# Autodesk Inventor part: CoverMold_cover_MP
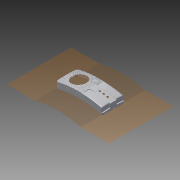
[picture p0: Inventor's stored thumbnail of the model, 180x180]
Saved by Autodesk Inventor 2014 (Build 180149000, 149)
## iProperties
Created: 2009-12
Part Number: CoverMold_cover_MP
Document SubType Name: Modeling
Designer: gaom
Density: 1 g/cm^3
Material: Generic
Appearance: Default
Author: gaom
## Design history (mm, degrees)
derived "cover.ipt"
node "CoverMold_cover_WP"
node "Hole Patch1"
patch "Boundary Patch1" dims "d7" = 10, "d8" = 0
node "Hole Patch2"
node "Hole Patch3"
patch "Boundary Patch2" dims "d9" = 10, "d10" = 10, "d11" = 10, "d12" = 10, "d13" = 0
node "Hole Patch4"
node "Runoff17" dims "Xmax" = 175, "Xmin" = -175, "Ymax" = 110, "Ymin" = -110, "Zmax" = 60, "Zmin" = -60
node "Runoff18" dims "Xmax" = 175, "Xmin" = -175, "Ymax" = 110, "Ymin" = -110, "Zmax" = 60, "Zmin" = -60
node "Runoff19" dims "Xmax" = 175, "Xmin" = -175, "Ymax" = 110, "Ymin" = -110, "Zmax" = 60, "Zmin" = -60
node "Runoff20" dims "Xmax" = 175, "Xmin" = -175, "Ymax" = 110, "Ymin" = -110, "Zmax" = 60, "Zmin" = -60
node "Runoff1" dims "Xmax" = 175, "Xmin" = -175, "Ymax" = 110, "Ymin" = -110, "Zmax" = 60, "Zmin" = -60
node "Runoff2" dims "Xmax" = 175, "Xmin" = -175, "Ymax" = 110, "Ymin" = -110, "Zmax" = 60, "Zmin" = -60
node "Runoff3" dims "Xmax" = 175, "Xmin" = -175, "Ymax" = 110, "Ymin" = -110, "Zmax" = 60, "Zmin" = -60
node "Runoff4" dims "Xmax" = 175, "Xmin" = -175, "Ymax" = 110, "Ymin" = -110, "Zmax" = 60, "Zmin" = -60
node "Runoff5" dims "Xmax" = 175, "Xmin" = -175, "Ymax" = 110, "Ymin" = -110, "Zmax" = 60, "Zmin" = -60
node "Runoff6" dims "Xmax" = 175, "Xmin" = -175, "Ymax" = 110, "Ymin" = -110, "Zmax" = 60, "Zmin" = -60
node "Runoff7" dims "Xmax" = 175, "Xmin" = -175, "Ymax" = 110, "Ymin" = -110, "Zmax" = 60, "Zmin" = -60
node "Runoff8" dims "Xmax" = 175, "Xmin" = -175, "Ymax" = 110, "Ymin" = -110, "Zmax" = 60, "Zmin" = -60
node "Runoff9" dims "Xmax" = 175, "Xmin" = -175, "Ymax" = 110, "Ymin" = -110, "Zmax" = 60, "Zmin" = -60
node "Runoff10" dims "Xmax" = 175, "Xmin" = -175, "Ymax" = 110, "Ymin" = -110, "Zmax" = 60, "Zmin" = -60
node "Runoff11" dims "Xmax" = 175, "Xmin" = -175, "Ymax" = 110, "Ymin" = -110, "Zmax" = 60, "Zmin" = -60
node "Runoff12" dims "Xmax" = 175, "Xmin" = -175, "Ymax" = 110, "Ymin" = -110, "Zmax" = 60, "Zmin" = -60
feature "Cavity Separation1"
node "CoverMold_cover_IN1_Base"
feature "Solid1::cover.ipt"
tag "TaggingFeature1"
feature "Solid1::CoverMold_cover_WP"
tag "TaggingFeature2"
body "Srf2"
body "Srf5"
body "Solid3"
body "Solid4"
feature "Solid1::CoverMold_cover_IN1_Base"
tag "TaggingFeature3"
body "Solid1"
body "Solid2"
feature "Surface1"
body "Srf1"
feature "Surface2"
body "Srf3"
feature "Surface3"
body "Srf4"
feature "Surface4"
body "Srf6"
feature "Surface5"
body "Srf7"
feature "Surface6"
body "Srf8"
feature "Surface7"
body "Srf9"
feature "Surface8"
body "Srf10"
feature "Surface9"
body "Srf11"
feature "Surface10"
body "Srf12"
feature "Surface11"
body "Srf13"
feature "Surface12"
body "Srf14"
feature "Surface13"
body "Srf15"
feature "Surface14"
body "Srf16"
feature "Surface15"
body "Srf17"
feature "Surface16"
body "Srf18"
feature "Surface21"
body "Srf23"
feature "Surface22"
body "Srf24"
feature "Surface23"
body "Srf25"
feature "Surface24"
body "Srf26"
body "Solid5"
other parameters: "d1" = 175, "d2" = 175, "d6" = 0
